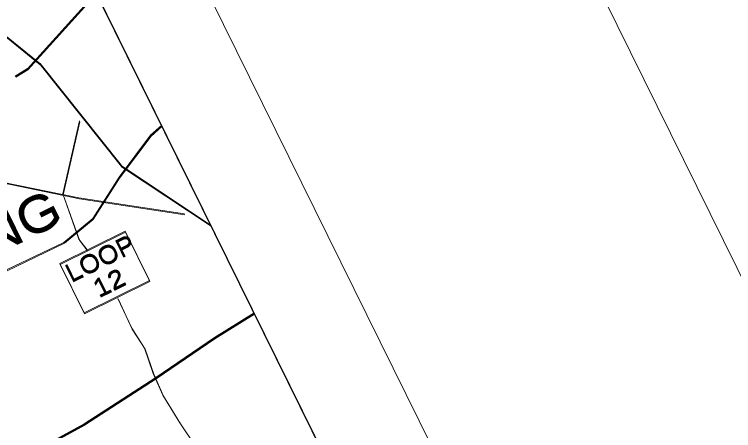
# Model space of a CAD drawing. Extents: x 2356606 to 2371222, y 6973096 to 6982644.
# Drawn here: x 2357437.7 to 2357641.7, y 6973761.2 to 6973879.3 of the extents above; entities that cross this region are included whole.
import ezdxf

# ---------------------------------------------------------------- set-up
doc = ezdxf.new("R2010")
doc.units = 0
doc.header["$LTSCALE"] = 2
doc.layers.add('62', color=7, linetype='Continuous', lineweight=13)
doc.layers.add('63', color=7, linetype='Continuous', lineweight=13)

msp = doc.modelspace()

# ---------------------------------------------------------------- linework, layer by layer
at = {"layer": '62'}
for p, q in [((2357367.886, 6974364.182), (2357723.359, 6973643.92)), ((2357278.212, 6974319.925), (2357633.685, 6973599.663)), ((2357456.191, 6973826.984), (2357434.377, 6973831.474)), ((2357456.191, 6973826.984), (2357486.116, 6973822.481)), ((2357456.181, 6973815.259), (2357458.479, 6973812.229))]:
    msp.add_line(p, q, dxfattribs=at)
at = {"layer": '62', "lineweight": 25}
msp.add_line((2357441.577, 6973863.558), (2357438.126, 6973861.454), dxfattribs=at)
for points in [[(2356999.05, 6973805.301), (2357204.965, 6973388.075), (2357608.13, 6973587.05), (2357402.214, 6974004.278)], [(2357441.577, 6973863.558), (2357460.265, 6973884.374), (2357461.041, 6973885.082)], [(2357428.062, 6973878.845), (2357445.085, 6973865.09), (2357468.122, 6973836.159), (2357493.515, 6973819.284)], [(2357505.855, 6973794.281), (2357494.638, 6973787.314), (2357477.945, 6973775.941), (2357457.618, 6973762.773), (2357434.819, 6973750.341), (2357408.769, 6973737.485), (2357380.527, 6973722.566), (2357364.72, 6973713.512)]]:
    msp.add_lwpolyline(points, dxfattribs=at)
at = {"layer": '62'}
for points in [[(2357371.211, 6973773.776), (2357382.807, 6973780.427), (2357402.976, 6973792.286), (2357422.585, 6973800.911), (2357435.675, 6973806.569), (2357451.93, 6973814.364), (2357460.097, 6973821.157), (2357467.581, 6973832.831), (2357476.49, 6973844.732), (2357479.572, 6973847.534)], [(2357456.181, 6973815.259), (2357451.597, 6973828.156), (2357456.303, 6973848.819)], [(2357526.798, 6973751.846), (2357517.36, 6973750.375), (2357501.195, 6973747.794), (2357489.256, 6973756.529), (2357484.812, 6973763.194), (2357480.012, 6973771.04), (2357477.267, 6973777.212), (2357474.788, 6973784.368), (2357471.174, 6973790.063), (2357467.234, 6973798.409)]]:
    msp.add_lwpolyline(points, dxfattribs=at)
msp.add_lwpolyline([(2357450.71, 6973808.393), (2357457.613, 6973794.412), (2357476.175, 6973803.573), (2357469.274, 6973817.557)], close=True, dxfattribs=at)
at = {"layer": '63', "lineweight": 25}
msp.add_line((2357441.447, 6973863.821), (2357437.996, 6973861.717), dxfattribs=at)
at = {"layer": '63'}
for p, q in [((2357456.061, 6973827.247), (2357434.247, 6973831.737)), ((2357456.061, 6973827.247), (2357485.986, 6973822.744)), ((2357456.051, 6973815.522), (2357458.349, 6973812.492))]:
    msp.add_line(p, q, dxfattribs=at)
at = {"layer": '63', "lineweight": 25}
for points in [[(2356998.92, 6973805.564), (2357204.835, 6973388.338), (2357608, 6973587.313), (2357402.084, 6974004.541)], [(2357441.447, 6973863.821), (2357460.135, 6973884.637), (2357460.911, 6973885.345)], [(2357427.932, 6973879.108), (2357444.955, 6973865.353), (2357467.992, 6973836.422), (2357493.385, 6973819.547)], [(2357505.725, 6973794.544), (2357494.508, 6973787.577), (2357477.815, 6973776.204), (2357457.488, 6973763.036), (2357434.689, 6973750.604), (2357408.639, 6973737.748), (2357380.397, 6973722.829), (2357364.59, 6973713.775)]]:
    msp.add_lwpolyline(points, dxfattribs=at)
at = {"layer": '63'}
for points in [[(2357371.081, 6973774.039), (2357382.677, 6973780.69), (2357402.846, 6973792.549), (2357422.455, 6973801.174), (2357435.545, 6973806.832), (2357451.8, 6973814.627), (2357459.967, 6973821.42), (2357467.451, 6973833.094), (2357476.36, 6973844.995), (2357479.442, 6973847.797)], [(2357456.051, 6973815.522), (2357451.467, 6973828.419), (2357456.173, 6973849.082)], [(2357526.668, 6973752.109), (2357517.23, 6973750.638), (2357501.065, 6973748.057), (2357489.126, 6973756.792), (2357484.682, 6973763.457), (2357479.882, 6973771.303), (2357477.137, 6973777.475), (2357474.658, 6973784.631), (2357471.044, 6973790.326), (2357467.104, 6973798.672)]]:
    msp.add_lwpolyline(points, dxfattribs=at)
msp.add_lwpolyline([(2357450.58, 6973808.656), (2357457.483, 6973794.675), (2357476.045, 6973803.836), (2357469.144, 6973817.82)], close=True, dxfattribs=at)

# ---------------------------------------------------------------- texts
at = {"layer": '62'}
for s, height, width, p in [('IRVING', 10.21, 1.15, (2357403.785, 6973796.752)), ('LOOP', 5.099, 1.1, (2357453.933, 6973803.035)), ('12', 5.099, 1.2, (2357461.719, 6973798.697))]:
    msp.add_text(s, height=height, rotation=26.268, dxfattribs=dict(at, width=width)).set_placement(p)
at = {"layer": '63'}
for s, height, width, p in [('IRVING', 10.21, 1.15, (2357403.655, 6973797.016)), ('LOOP', 5.099, 1.1, (2357453.803, 6973803.299)), ('12', 5.099, 1.2, (2357461.589, 6973798.961))]:
    msp.add_text(s, height=height, rotation=26.268, dxfattribs=dict(at, width=width)).set_placement(p)

doc.saveas('drawing.dxf')
